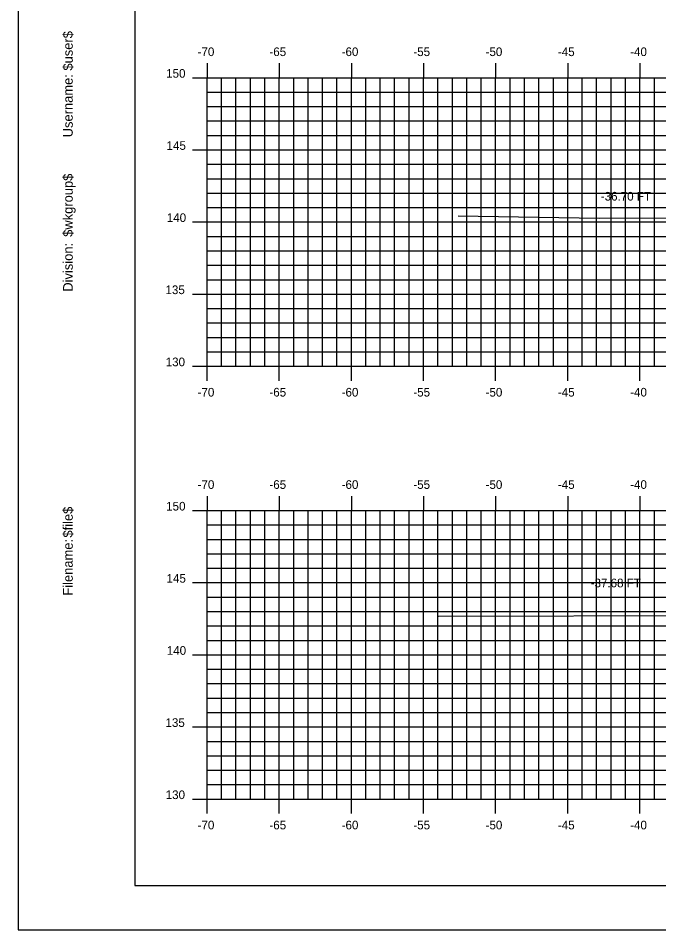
# Model space of a CAD drawing. Extents: x 1145194 to 1145364, y 608981 to 609091.
# Drawn here: x 1145194 to 1145238.4, y 608981.3 to 609044.5 of the extents above; entities that cross this region are included whole.
import ezdxf

# ---------------------------------------------------------------- set-up
doc = ezdxf.new("R2010")
doc.units = 0
for name, color, linetype in [('BORDER', 7, 'Continuous'), ('D_Text_Standard', 7, 'Continuous'), ('H_V ANNOTATION', 7, 'Continuous'), ('MAJOR', 7, 'Continuous'), ('MINOR', 7, 'Continuous'), ('PLOT BOUNDARY', 7, 'Continuous'), ('S_Roadway_Centerline', 7, 'Continuous')]:
    doc.layers.add(name, color=color, linetype=linetype)

msp = doc.modelspace()

# ---------------------------------------------------------------- linework, layer by layer
at = {"layer": 'BORDER'}
msp.add_lwpolyline([(1145202.132, 608984.335), (1145362.132, 608984.335), (1145362.132, 609089.335), (1145202.132, 609089.335)], close=True, dxfattribs=at)
at = {"layer": 'MAJOR'}
for p, q in [((1145207.132, 609041.337), (1145207.132, 609040.335)), ((1145212.132, 609041.337), (1145212.132, 609040.335)), ((1145217.132, 609041.337), (1145217.132, 609040.335)), ((1145222.132, 609041.337), (1145222.132, 609040.335)), ((1145227.132, 609041.337), (1145227.132, 609040.335)), ((1145232.132, 609041.337), (1145232.132, 609040.335)), ((1145237.132, 609041.337), (1145237.132, 609040.335)), ((1145206.13, 609040.335), (1145207.132, 609040.335)), ((1145207.132, 609040.335), (1145347.132, 609040.335)), ((1145207.132, 609020.335), (1145207.132, 609040.335)), ((1145207.132, 609020.335), (1145207.132, 609040.335)), ((1145207.132, 609040.335), (1145347.132, 609040.335)), ((1145212.132, 609020.335), (1145212.132, 609040.335)), ((1145217.132, 609020.335), (1145217.132, 609040.335)), ((1145222.132, 609020.335), (1145222.132, 609040.335)), ((1145227.132, 609020.335), (1145227.132, 609040.335)), ((1145232.132, 609020.335), (1145232.132, 609040.335)), ((1145237.132, 609020.335), (1145237.132, 609040.335)), ((1145206.13, 609035.335), (1145207.132, 609035.335)), ((1145207.132, 609035.335), (1145347.132, 609035.335)), ((1145206.13, 609030.335), (1145207.132, 609030.335)), ((1145207.132, 609030.335), (1145347.132, 609030.335)), ((1145206.13, 609025.335), (1145207.132, 609025.335)), ((1145207.132, 609025.335), (1145347.132, 609025.335)), ((1145206.13, 609020.335), (1145207.132, 609020.335)), ((1145207.132, 609020.335), (1145347.132, 609020.335)), ((1145207.132, 609020.335), (1145347.132, 609020.335)), ((1145207.132, 609019.333), (1145207.132, 609020.335)), ((1145212.132, 609019.333), (1145212.132, 609020.335)), ((1145217.132, 609019.333), (1145217.132, 609020.335)), ((1145222.132, 609019.333), (1145222.132, 609020.335)), ((1145227.132, 609019.333), (1145227.132, 609020.335)), ((1145232.132, 609019.333), (1145232.132, 609020.335)), ((1145237.132, 609019.333), (1145237.132, 609020.335)), ((1145207.132, 609011.337), (1145207.132, 609010.335)), ((1145212.132, 609011.337), (1145212.132, 609010.335)), ((1145217.132, 609011.337), (1145217.132, 609010.335)), ((1145222.132, 609011.337), (1145222.132, 609010.335)), ((1145227.132, 609011.337), (1145227.132, 609010.335)), ((1145232.132, 609011.337), (1145232.132, 609010.335)), ((1145237.132, 609011.337), (1145237.132, 609010.335)), ((1145206.13, 609010.335), (1145207.132, 609010.335)), ((1145207.132, 609010.335), (1145347.132, 609010.335)), ((1145207.132, 608990.335), (1145207.132, 609010.335)), ((1145207.132, 608990.335), (1145207.132, 609010.335)), ((1145207.132, 609010.335), (1145347.132, 609010.335)), ((1145212.132, 608990.335), (1145212.132, 609010.335)), ((1145217.132, 608990.335), (1145217.132, 609010.335)), ((1145222.132, 608990.335), (1145222.132, 609010.335)), ((1145227.132, 608990.335), (1145227.132, 609010.335)), ((1145232.132, 608990.335), (1145232.132, 609010.335)), ((1145237.132, 608990.335), (1145237.132, 609010.335)), ((1145206.13, 609005.335), (1145207.132, 609005.335)), ((1145207.132, 609005.335), (1145347.132, 609005.335)), ((1145206.13, 609000.335), (1145207.132, 609000.335)), ((1145207.132, 609000.335), (1145347.132, 609000.335)), ((1145206.13, 608995.335), (1145207.132, 608995.335)), ((1145207.132, 608995.335), (1145347.132, 608995.335)), ((1145206.13, 608990.335), (1145207.132, 608990.335)), ((1145207.132, 608990.335), (1145347.132, 608990.335)), ((1145207.132, 608990.335), (1145347.132, 608990.335)), ((1145207.132, 608989.333), (1145207.132, 608990.335)), ((1145212.132, 608989.333), (1145212.132, 608990.335)), ((1145217.132, 608989.333), (1145217.132, 608990.335)), ((1145222.132, 608989.333), (1145222.132, 608990.335)), ((1145227.132, 608989.333), (1145227.132, 608990.335)), ((1145232.132, 608989.333), (1145232.132, 608990.335)), ((1145237.132, 608989.333), (1145237.132, 608990.335))]:
    msp.add_line(p, q, dxfattribs=at)
at = {"layer": 'MINOR'}
for p, q in [((1145208.132, 609020.335), (1145208.132, 609040.335)), ((1145209.132, 609020.335), (1145209.132, 609040.335)), ((1145210.132, 609020.335), (1145210.132, 609040.335)), ((1145211.132, 609020.335), (1145211.132, 609040.335)), ((1145213.132, 609020.335), (1145213.132, 609040.335)), ((1145214.132, 609020.335), (1145214.132, 609040.335)), ((1145215.132, 609020.335), (1145215.132, 609040.335)), ((1145216.132, 609020.335), (1145216.132, 609040.335)), ((1145218.132, 609020.335), (1145218.132, 609040.335)), ((1145219.132, 609020.335), (1145219.132, 609040.335)), ((1145220.132, 609020.335), (1145220.132, 609040.335)), ((1145221.132, 609020.335), (1145221.132, 609040.335)), ((1145223.132, 609020.335), (1145223.132, 609040.335)), ((1145224.132, 609020.335), (1145224.132, 609040.335)), ((1145225.132, 609020.335), (1145225.132, 609040.335)), ((1145226.132, 609020.335), (1145226.132, 609040.335)), ((1145228.132, 609020.335), (1145228.132, 609040.335)), ((1145229.132, 609020.335), (1145229.132, 609040.335)), ((1145230.132, 609020.335), (1145230.132, 609040.335)), ((1145231.132, 609020.335), (1145231.132, 609040.335)), ((1145233.132, 609020.335), (1145233.132, 609040.335)), ((1145234.132, 609020.335), (1145234.132, 609040.335)), ((1145235.132, 609020.335), (1145235.132, 609040.335)), ((1145236.132, 609020.335), (1145236.132, 609040.335)), ((1145238.132, 609020.335), (1145238.132, 609040.335)), ((1145207.132, 609039.335), (1145347.132, 609039.335)), ((1145207.132, 609039.335), (1145208.134, 609039.335)), ((1145207.132, 609038.335), (1145347.132, 609038.335)), ((1145207.132, 609038.335), (1145208.134, 609038.335)), ((1145207.132, 609037.335), (1145347.132, 609037.335)), ((1145207.132, 609037.335), (1145208.134, 609037.335)), ((1145207.132, 609036.335), (1145347.132, 609036.335)), ((1145207.132, 609036.335), (1145208.134, 609036.335)), ((1145207.132, 609034.335), (1145347.132, 609034.335)), ((1145207.132, 609034.335), (1145208.134, 609034.335)), ((1145207.132, 609033.335), (1145347.132, 609033.335)), ((1145207.132, 609033.335), (1145208.134, 609033.335)), ((1145207.132, 609032.335), (1145347.132, 609032.335)), ((1145207.132, 609032.335), (1145208.134, 609032.335)), ((1145207.132, 609031.335), (1145347.132, 609031.335)), ((1145207.132, 609031.335), (1145208.134, 609031.335)), ((1145207.132, 609029.335), (1145347.132, 609029.335)), ((1145207.132, 609029.335), (1145208.134, 609029.335)), ((1145207.132, 609028.335), (1145347.132, 609028.335)), ((1145207.132, 609028.335), (1145208.134, 609028.335)), ((1145207.132, 609027.335), (1145347.132, 609027.335)), ((1145207.132, 609027.335), (1145208.134, 609027.335)), ((1145207.132, 609026.335), (1145347.132, 609026.335)), ((1145207.132, 609026.335), (1145208.134, 609026.335)), ((1145207.132, 609024.335), (1145347.132, 609024.335)), ((1145207.132, 609024.335), (1145208.134, 609024.335)), ((1145207.132, 609023.335), (1145347.132, 609023.335)), ((1145207.132, 609023.335), (1145208.134, 609023.335)), ((1145207.132, 609022.335), (1145347.132, 609022.335)), ((1145207.132, 609022.335), (1145208.134, 609022.335)), ((1145207.132, 609021.335), (1145347.132, 609021.335)), ((1145207.132, 609021.335), (1145208.134, 609021.335)), ((1145208.132, 608990.335), (1145208.132, 609010.335)), ((1145209.132, 608990.335), (1145209.132, 609010.335)), ((1145210.132, 608990.335), (1145210.132, 609010.335)), ((1145211.132, 608990.335), (1145211.132, 609010.335)), ((1145213.132, 608990.335), (1145213.132, 609010.335)), ((1145214.132, 608990.335), (1145214.132, 609010.335)), ((1145215.132, 608990.335), (1145215.132, 609010.335)), ((1145216.132, 608990.335), (1145216.132, 609010.335)), ((1145218.132, 608990.335), (1145218.132, 609010.335)), ((1145219.132, 608990.335), (1145219.132, 609010.335)), ((1145220.132, 608990.335), (1145220.132, 609010.335)), ((1145221.132, 608990.335), (1145221.132, 609010.335)), ((1145223.132, 608990.335), (1145223.132, 609010.335)), ((1145224.132, 608990.335), (1145224.132, 609010.335)), ((1145225.132, 608990.335), (1145225.132, 609010.335)), ((1145226.132, 608990.335), (1145226.132, 609010.335)), ((1145228.132, 608990.335), (1145228.132, 609010.335)), ((1145229.132, 608990.335), (1145229.132, 609010.335)), ((1145230.132, 608990.335), (1145230.132, 609010.335)), ((1145231.132, 608990.335), (1145231.132, 609010.335)), ((1145233.132, 608990.335), (1145233.132, 609010.335)), ((1145234.132, 608990.335), (1145234.132, 609010.335)), ((1145235.132, 608990.335), (1145235.132, 609010.335)), ((1145236.132, 608990.335), (1145236.132, 609010.335)), ((1145238.132, 608990.335), (1145238.132, 609010.335)), ((1145207.132, 609009.335), (1145347.132, 609009.335)), ((1145207.132, 609009.335), (1145208.134, 609009.335)), ((1145207.132, 609008.335), (1145347.132, 609008.335)), ((1145207.132, 609008.335), (1145208.134, 609008.335)), ((1145207.132, 609007.335), (1145347.132, 609007.335)), ((1145207.132, 609007.335), (1145208.134, 609007.335)), ((1145207.132, 609006.335), (1145347.132, 609006.335)), ((1145207.132, 609006.335), (1145208.134, 609006.335)), ((1145207.132, 609004.335), (1145347.132, 609004.335)), ((1145207.132, 609004.335), (1145208.134, 609004.335)), ((1145207.132, 609003.335), (1145347.132, 609003.335)), ((1145207.132, 609003.335), (1145208.134, 609003.335)), ((1145207.132, 609002.335), (1145347.132, 609002.335)), ((1145207.132, 609002.335), (1145208.134, 609002.335)), ((1145207.132, 609001.335), (1145347.132, 609001.335)), ((1145207.132, 609001.335), (1145208.134, 609001.335)), ((1145207.132, 608999.335), (1145347.132, 608999.335)), ((1145207.132, 608999.335), (1145208.134, 608999.335)), ((1145207.132, 608998.335), (1145347.132, 608998.335)), ((1145207.132, 608998.335), (1145208.134, 608998.335)), ((1145207.132, 608997.335), (1145347.132, 608997.335)), ((1145207.132, 608997.335), (1145208.134, 608997.335)), ((1145207.132, 608996.335), (1145347.132, 608996.335)), ((1145207.132, 608996.335), (1145208.134, 608996.335)), ((1145207.132, 608994.335), (1145347.132, 608994.335)), ((1145207.132, 608994.335), (1145208.134, 608994.335)), ((1145207.132, 608993.335), (1145347.132, 608993.335)), ((1145207.132, 608993.335), (1145208.134, 608993.335)), ((1145207.132, 608992.335), (1145347.132, 608992.335)), ((1145207.132, 608992.335), (1145208.134, 608992.335)), ((1145207.132, 608991.335), (1145347.132, 608991.335)), ((1145207.132, 608991.335), (1145208.134, 608991.335))]:
    msp.add_line(p, q, dxfattribs=at)
at = {"layer": 'PLOT BOUNDARY'}
msp.add_lwpolyline([(1145194.039, 608981.276), (1145364.039, 608981.276), (1145364.039, 609091.276), (1145194.039, 609091.276)], close=True, dxfattribs=at)
at = {"layer": 'S_Roadway_Centerline'}
for points in [[(1145224.528, 609030.772), (1145234.304, 609030.604), (1145249.208, 609030.65), (1145252.864, 609029.757), (1145257.166, 609028.889), (1145258.819, 609029.378), (1145260.888, 609029.886), (1145261.776, 609029.943), (1145262.584, 609029.963), (1145270.874, 609030.127), (1145273.9, 609030.196), (1145281.879, 609029.922), (1145284.812, 609029.858), (1145287.669, 609029.57), (1145288.499, 609029.477), (1145291.49, 609028.782), (1145292.645, 609028.588), (1145294.997, 609029.318), (1145299.578, 609030.541), (1145307.466, 609030.879), (1145323.345, 609031.482)], [(1145223.166, 609003.006), (1145241.903, 609003.066), (1145248.778, 609002.948), (1145254.838, 609001.419), (1145256.893, 609000.916), (1145259.182, 609001.542), (1145260.082, 609001.809), (1145262.139, 609001.946), (1145262.599, 609001.976), (1145271.221, 609002.19), (1145273.977, 609002.245), (1145276.689, 609002.152), (1145284.89, 609001.824), (1145287.007, 609001.621), (1145287.938, 609001.527), (1145288.943, 609001.294), (1145292.925, 609000.571), (1145297.727, 609001.626), (1145299.356, 609002.061), (1145320.182, 609002.692), (1145322.779, 609002.793)]]:
    msp.add_lwpolyline(points, dxfattribs=at)

# ---------------------------------------------------------------- texts
at = {"layer": 'BORDER'}
for s, p in [('$user$', (1145197.817, 609040.827)), ('Username:', (1145197.817, 609036.203)), ('$wkgroup$', (1145197.817, 609029.305)), ('Division:', (1145197.817, 609025.501)), ('$file$', (1145197.817, 609008.461)), ('Filename:', (1145197.817, 609004.433))]:
    msp.add_text(s, height=0.6696, rotation=90, dxfattribs=at).set_placement(p)
at = {"layer": 'D_Text_Standard'}
for s, p in [('-36.70 FT', (1145234.422, 609031.819)), ('-37.68 FT', (1145233.72, 609005.013))]:
    msp.add_text(s, height=0.6, dxfattribs=at).set_placement(p)
at = {"layer": 'H_V ANNOTATION'}
for s, p in [('-70', (1145206.474, 609041.835)), ('-65', (1145211.45, 609041.835)), ('-60', (1145216.458, 609041.835)), ('-55', (1145221.428, 609041.835)), ('-50', (1145226.436, 609041.835)), ('-45', (1145231.45, 609041.835)), ('-40', (1145236.458, 609041.835)), ('150', (1145204.294, 609040.335)), ('145', (1145204.321, 609035.335)), ('140', (1145204.337, 609030.335)), ('135', (1145204.246, 609025.335)), ('130', (1145204.262, 609020.335)), ('-70', (1145206.474, 609018.235)), ('-65', (1145211.45, 609018.235)), ('-60', (1145216.458, 609018.235)), ('-55', (1145221.428, 609018.235)), ('-50', (1145226.436, 609018.235)), ('-45', (1145231.45, 609018.235)), ('-40', (1145236.458, 609018.235)), ('-70', (1145206.474, 609011.835)), ('-65', (1145211.45, 609011.835)), ('-60', (1145216.458, 609011.835)), ('-55', (1145221.428, 609011.835)), ('-50', (1145226.436, 609011.835)), ('-45', (1145231.45, 609011.835)), ('-40', (1145236.458, 609011.835)), ('150', (1145204.294, 609010.335)), ('145', (1145204.321, 609005.335)), ('140', (1145204.337, 609000.335)), ('135', (1145204.246, 608995.335)), ('130', (1145204.262, 608990.335)), ('-70', (1145206.474, 608988.235)), ('-65', (1145211.45, 608988.235)), ('-60', (1145216.458, 608988.235)), ('-55', (1145221.428, 608988.235)), ('-50', (1145226.436, 608988.235)), ('-45', (1145231.45, 608988.235)), ('-40', (1145236.458, 608988.235))]:
    msp.add_text(s, height=0.6, dxfattribs=at).set_placement(p)
at = {"layer": 'MAJOR'}
for p in [(1145207.128, 609020.335), (1145207.128, 608990.335)]:
    msp.add_text('-', height=0.006, dxfattribs=at).set_placement(p)

doc.saveas('drawing.dxf')
